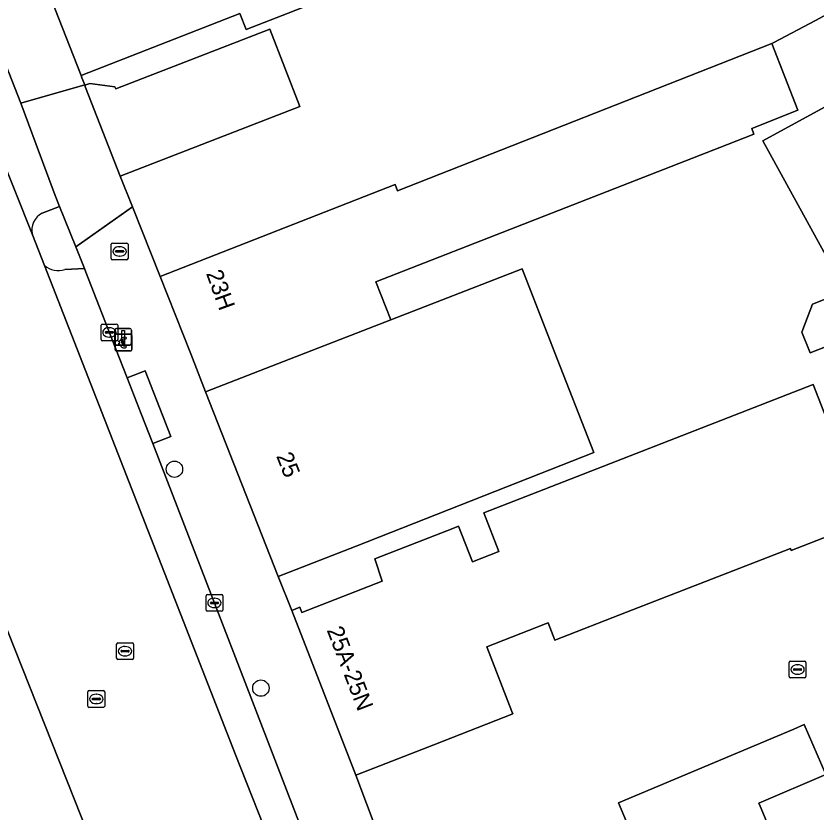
# Model space of a CAD drawing. Extents: x 161087 to 161926, y 382572 to 383873.
# Drawn here: x 161741.12 to 161788.94, y 382710.1 to 382757.68 of the extents above; entities that cross this region are included whole.
import ezdxf

# ---------------------------------------------------------------- set-up
doc = ezdxf.new("R2010")
doc.units = 0
for name, color, linetype in [('IMGEO_Betaalautomaat', 7, 'Continuous'), ('IMGEO_Boom', 7, 'Continuous'), ('IMGEO_Brandkraan', 7, 'Continuous'), ('IMGEO_Erf', 7, 'Continuous'), ('IMGEO_Kolk', 7, 'Continuous'), ('IMGEO_Lichtmast', 7, 'Continuous'), ('IMGEO_Pand', 7, 'Continuous'), ('IMGEO_Pand_nummerreeks', 7, 'Continuous'), ('IMGEO_Pand_overbouw', 7, 'Continuous'), ('IMGEO_Parkeervlak_open', 7, 'Continuous'), ('IMGEO_Rijbaan_lokaal_open', 7, 'Continuous'), ('IMGEO_Rioolput', 7, 'Continuous'), ('IMGEO_Voetpad_open', 7, 'Continuous')]:
    doc.layers.add(name, color=color, linetype=linetype)

msp = doc.modelspace()

# ---------------------------------------------------------------- linework, layer by layer
at = {"layer": 'IMGEO_Betaalautomaat'}
for p, q in [((161747.115, 382738.666), (161747.956, 382738.666)), ((161747.956, 382738.666), (161747.115, 382738.666)), ((161747.04, 382737.742), (161747.04, 382738.583)), ((161747.04, 382738.583), (161747.04, 382737.742)), ((161747.323, 382738.13), (161747.323, 382738.198)), ((161747.444, 382738.198), (161747.444, 382738.13)), ((161747.702, 382738.471), (161747.685, 382738.371)), ((161748.039, 382738.592), (161748.039, 382737.751)), ((161748.039, 382737.751), (161748.039, 382738.592)), ((161747.689, 382737.965), (161747.711, 382737.878)), ((161747.965, 382737.667), (161747.124, 382737.667)), ((161747.124, 382737.667), (161747.965, 382737.667))]:
    msp.add_line(p, q, dxfattribs=at)
for points in [[(161747.323, 382738.198), (161747.254, 382738.198), (161747.254, 382738.267), (161747.333, 382738.267)], [(161747.455, 382738.267), (161747.602, 382738.267), (161747.602, 382738.198), (161747.444, 382738.198)], [(161747.328, 382738.061), (161747.254, 382738.061), (161747.254, 382738.13), (161747.323, 382738.13)], [(161747.444, 382738.13), (161747.602, 382738.13), (161747.602, 382738.061), (161747.458, 382738.061)]]:
    msp.add_lwpolyline(points, dxfattribs=at)
for centre, radius, start, end in [((161747.118, 382738.589), 0.0779, 92.4484, 184.2845), ((161747.118, 382738.589), 0.0779, 92.4484, 184.2845), ((161747.962, 382738.589), 0.0779, 2.4484, 94.2845), ((161747.962, 382738.589), 0.0779, 2.4484, 94.2845), ((161747.616, 382738.191), 0.293, 73.014, 165.0139), ((161747.622, 382738.204), 0.179, 69.3236, 159.5683), ((161747.118, 382737.745), 0.0779, 182.4484, 274.2845), ((161747.118, 382737.745), 0.0779, 182.4484, 274.2845), ((161747.589, 382738.116), 0.267, 191.8096, 297.0389), ((161747.622, 382738.131), 0.179, 202.7625, 291.8693), ((161747.962, 382737.745), 0.0779, 272.4484, 4.2845), ((161747.962, 382737.745), 0.0779, 272.4484, 4.2845)]:
    msp.add_arc(centre, radius, start, end, dxfattribs=at)
at = {"layer": 'IMGEO_Boom'}
for centre in [(161750.589, 382730.591), (161755.753, 382717.503)]:
    msp.add_circle(centre, 0.489, dxfattribs=at)
at = {"layer": 'IMGEO_Brandkraan'}
for p, q in [((161746.811, 382743.187), (161746.811, 382744.039)), ((161746.886, 382744.113), (161747.738, 382744.113)), ((161747.812, 382744.039), (161747.812, 382743.187)), ((161747.07, 382743.607), (161747.07, 382743.619)), ((161747.508, 382743.57), (161747.11, 382743.57)), ((161747.113, 382743.656), (161747.511, 382743.656)), ((161747.299, 382743.893), (161747.324, 382743.893)), ((161747.554, 382743.619), (161747.554, 382743.607)), ((161747.738, 382743.113), (161746.886, 382743.113)), ((161747.322, 382743.333), (161747.297, 382743.333))]:
    msp.add_line(p, q, dxfattribs=at)
for points in [[(161746.811, 382743.187), (161746.811, 382744.039)], [(161746.886, 382744.113), (161747.738, 382744.113)], [(161747.812, 382744.039), (161747.812, 382743.187)], [(161747.738, 382743.113), (161746.886, 382743.113)]]:
    msp.add_lwpolyline(points, dxfattribs=at)
for centre, radius, start, end in [((161746.888, 382744.037), 0.0765, 91.552, 178.448), ((161746.888, 382744.037), 0.0765, 91.552, 178.448), ((161747.736, 382744.037), 0.0765, 1.552, 88.448), ((161747.736, 382744.037), 0.0765, 1.552, 88.448), ((161747.11, 382743.616), 0.0403, 85.8775, 175.7526), ((161747.107, 382743.606), 0.0366, 178.938, 274.7102), ((161747.511, 382743.613), 0.043, 264.8664, 352.4533), ((161747.515, 382743.618), 0.0386, 1.7309, 96.639), ((161746.888, 382743.189), 0.0765, 181.552, 268.448), ((161746.888, 382743.189), 0.0765, 181.552, 268.448), ((161747.736, 382743.189), 0.0765, 271.552, 358.448), ((161747.736, 382743.189), 0.0765, 271.552, 358.448)]:
    msp.add_arc(centre, radius, start, end, dxfattribs=at)
for centre, major_axis, ratio, start_param, end_param in [((161747.298, 382743.613), (-0.387, 0.002), 0.722429, 4.712389, 7.853982), ((161747.323, 382743.613), (-0.39, 0.002), 0.717154, 1.570796, 4.712389)]:
    msp.add_ellipse(centre, major_axis=major_axis, ratio=ratio, start_param=start_param, end_param=end_param, dxfattribs=at)
at = {"layer": 'IMGEO_Erf'}
for points in [[(161792.002, 382759.112), (161788.908, 382757.413), (161786.424, 382756.091), (161786.294, 382756.038), (161787.843, 382752.05), (161785.092, 382750.952), (161785.222, 382750.626), (161783.647, 382750), (161762.633, 382741.801), (161763.515, 382739.519), (161771.376, 382742.575), (161773.294, 382737.652), (161775.656, 382731.589), (161769.742, 382729.263), (161761.442, 382725.999), (161756.788, 382724.168), (161757.599, 382722.152), (161758.076, 382722.338), (161758.198, 382722.024), (161762.996, 382723.894), (161762.56, 382725.236), (161767.219, 382727.052), (161767.568, 382727.188), (161768.401, 382725.051), (161769.983, 382725.667), (161769.081, 382727.983), (161772.311, 382729.242), (161788.77, 382735.655), (161791.956, 382727.48), (161787.457, 382725.726), (161787.405, 382725.859), (161777.602, 382722.04), (161773.321, 382720.372), (161772.921, 382721.4), (161772.775, 382721.343), (161771.752, 382720.945), (161769.259, 382719.973), (161770.763, 382716.112), (161770.821, 382715.962), (161766.092, 382714.119), (161761.433, 382712.304), (161771.278, 382686.152)], [(161778.153, 382708.232), (161777.137, 382710.655), (161787.603, 382715.06), (161788.237, 382715.327), (161789.523, 382712.339), (161785.528, 382710.619), (161785.598, 382710.452), (161787.258, 382706.492)]]:
    msp.add_lwpolyline(points, dxfattribs=at)
for points in [[(161758.09, 382752.271), (161756.299, 382756.897), (161747.078, 382753.327), (161747.027, 382753.458), (161745.521, 382753.653), (161745.232, 382753.541), (161745.281, 382753.416), (161747.346, 382748.113)], [(161797.962, 382728.415), (161797.788, 382728.319), (161785.753, 382750.218), (161791.191, 382753.197), (161793.435, 382754.427), (161794.2, 382753.036), (161798.607, 382745.023), (161799.005, 382744.299), (161797.372, 382743.432), (161798.28, 382741.775), (161799.902, 382742.664), (161800.287, 382741.962), (161804.675, 382733.953), (161805.453, 382732.533)], [(161788.579, 382737.55), (161788.088, 382738.792), (161788.733, 382740.452), (161790.249, 382741.048), (161791.235, 382738.594)]]:
    msp.add_lwpolyline(points, close=True, dxfattribs=at)
at = {"layer": 'IMGEO_Kolk'}
for p, q in [((161746.198, 382738.345), (161746.198, 382739.197)), ((161746.273, 382739.271), (161747.125, 382739.271)), ((161747.199, 382739.197), (161747.199, 382738.345)), ((161746.457, 382738.765), (161746.457, 382738.777)), ((161746.895, 382738.728), (161746.497, 382738.728)), ((161746.5, 382738.814), (161746.898, 382738.814)), ((161746.686, 382739.051), (161746.711, 382739.051)), ((161746.941, 382738.777), (161746.941, 382738.765)), ((161747.125, 382738.271), (161746.273, 382738.271)), ((161746.709, 382738.491), (161746.684, 382738.491)), ((161752.476, 382722.17), (161752.476, 382723.022)), ((161752.551, 382723.096), (161753.403, 382723.096)), ((161752.964, 382722.876), (161752.989, 382722.876)), ((161753.477, 382723.022), (161753.477, 382722.17)), ((161752.735, 382722.59), (161752.735, 382722.602)), ((161753.173, 382722.553), (161752.775, 382722.553)), ((161752.778, 382722.639), (161753.176, 382722.639)), ((161753.219, 382722.602), (161753.219, 382722.59)), ((161753.403, 382722.096), (161752.551, 382722.096)), ((161752.987, 382722.316), (161752.962, 382722.316)), ((161787.335, 382718.192), (161787.335, 382719.044)), ((161787.41, 382719.118), (161788.262, 382719.118)), ((161788.336, 382719.044), (161788.336, 382718.192)), ((161787.594, 382718.612), (161787.594, 382718.624)), ((161788.032, 382718.575), (161787.634, 382718.575)), ((161787.637, 382718.661), (161788.035, 382718.661)), ((161787.823, 382718.898), (161787.848, 382718.898)), ((161788.078, 382718.624), (161788.078, 382718.612)), ((161788.262, 382718.118), (161787.41, 382718.118)), ((161787.846, 382718.338), (161787.821, 382718.338))]:
    msp.add_line(p, q, dxfattribs=at)
for points in [[(161746.198, 382738.345), (161746.198, 382739.197)], [(161746.273, 382739.271), (161747.125, 382739.271)], [(161747.199, 382739.197), (161747.199, 382738.345)], [(161747.125, 382738.271), (161746.273, 382738.271)], [(161752.476, 382722.17), (161752.476, 382723.022)], [(161752.551, 382723.096), (161753.403, 382723.096)], [(161753.477, 382723.022), (161753.477, 382722.17)], [(161753.403, 382722.096), (161752.551, 382722.096)], [(161787.335, 382718.192), (161787.335, 382719.044)], [(161787.41, 382719.118), (161788.262, 382719.118)], [(161788.336, 382719.044), (161788.336, 382718.192)], [(161788.262, 382718.118), (161787.41, 382718.118)]]:
    msp.add_lwpolyline(points, dxfattribs=at)
for centre, radius, start, end in [((161746.275, 382739.195), 0.0765, 91.552, 178.448), ((161746.275, 382739.195), 0.0765, 91.552, 178.448), ((161747.123, 382739.195), 0.0765, 1.552, 88.448), ((161747.123, 382739.195), 0.0765, 1.552, 88.448), ((161746.497, 382738.774), 0.0403, 85.8775, 175.7526), ((161746.494, 382738.764), 0.0366, 178.938, 274.7102), ((161746.898, 382738.771), 0.043, 264.8664, 352.4533), ((161746.902, 382738.776), 0.0386, 1.7309, 96.639), ((161746.275, 382738.347), 0.0765, 181.552, 268.448), ((161746.275, 382738.347), 0.0765, 181.552, 268.448), ((161747.123, 382738.347), 0.0765, 271.552, 358.448), ((161747.123, 382738.347), 0.0765, 271.552, 358.448), ((161752.553, 382723.02), 0.0765, 91.552, 178.448), ((161752.553, 382723.02), 0.0765, 91.552, 178.448), ((161753.401, 382723.02), 0.0765, 1.552, 88.448), ((161753.401, 382723.02), 0.0765, 1.552, 88.448), ((161752.775, 382722.599), 0.0403, 85.8775, 175.7526), ((161752.772, 382722.589), 0.0366, 178.938, 274.7102), ((161753.176, 382722.596), 0.043, 264.8664, 352.4533), ((161753.18, 382722.601), 0.0386, 1.7309, 96.639), ((161752.553, 382722.172), 0.0765, 181.552, 268.448), ((161752.553, 382722.172), 0.0765, 181.552, 268.448), ((161753.401, 382722.172), 0.0765, 271.552, 358.448), ((161753.401, 382722.172), 0.0765, 271.552, 358.448), ((161787.412, 382719.042), 0.0765, 91.552, 178.448), ((161787.412, 382719.042), 0.0765, 91.552, 178.448), ((161788.26, 382719.042), 0.0765, 1.552, 88.448), ((161788.26, 382719.042), 0.0765, 1.552, 88.448), ((161787.634, 382718.621), 0.0403, 85.8775, 175.7526), ((161787.631, 382718.611), 0.0366, 178.938, 274.7102), ((161788.035, 382718.618), 0.043, 264.8664, 352.4533), ((161788.039, 382718.623), 0.0386, 1.7309, 96.639), ((161787.412, 382718.194), 0.0765, 181.552, 268.448), ((161787.412, 382718.194), 0.0765, 181.552, 268.448), ((161788.26, 382718.194), 0.0765, 271.552, 358.448), ((161788.26, 382718.194), 0.0765, 271.552, 358.448)]:
    msp.add_arc(centre, radius, start, end, dxfattribs=at)
for centre, major_axis, ratio, start_param, end_param in [((161746.685, 382738.771), (-0.387, 0.002), 0.722429, 4.712389, 7.853982), ((161746.71, 382738.771), (-0.39, 0.002), 0.717154, 1.570796, 4.712389), ((161752.963, 382722.596), (-0.387, 0.002), 0.722429, 4.712389, 7.853982), ((161752.988, 382722.596), (-0.39, 0.002), 0.717154, 1.570796, 4.712389), ((161787.822, 382718.618), (-0.387, 0.002), 0.722429, 4.712389, 7.853982), ((161787.847, 382718.618), (-0.39, 0.002), 0.717154, 1.570796, 4.712389)]:
    msp.add_ellipse(centre, major_axis=major_axis, ratio=ratio, start_param=start_param, end_param=end_param, dxfattribs=at)
at = {"layer": 'IMGEO_Lichtmast'}
for p, q in [((161747.029, 382738.109), (161747.029, 382738.909)), ((161747.029, 382738.909), (161747.029, 382738.109)), ((161747.129, 382739.009), (161747.919, 382739.009)), ((161747.919, 382739.009), (161747.129, 382739.009)), ((161748.019, 382738.909), (161748.019, 382738.109)), ((161748.019, 382738.109), (161748.019, 382738.909)), ((161747.919, 382738.009), (161747.129, 382738.009)), ((161747.129, 382738.009), (161747.919, 382738.009))]:
    msp.add_line(p, q, dxfattribs=at)
msp.add_lwpolyline([(161747.449, 382738.884), (161747.599, 382738.884), (161747.599, 382738.134), (161747.449, 382738.134), (161747.449, 382738.884)], dxfattribs=at)
for centre, start, end in [((161747.129, 382738.909), 90, 180), ((161747.129, 382738.909), 90, 180), ((161747.919, 382738.909), 0, 90), ((161747.919, 382738.909), 360, 90), ((161747.129, 382738.109), 180, 270), ((161747.129, 382738.109), 180, 270), ((161747.919, 382738.109), 270, 0), ((161747.919, 382738.109), 270, 0)]:
    msp.add_arc(centre, 0.1, start, end, dxfattribs=at)
at = {"layer": 'IMGEO_Pand'}
for points in [[(161778.916, 382776.105), (161778.137, 382776.023), (161774.502, 382785.469), (161764.744, 382784.333), (161765.335, 382779.309), (161753.095, 382778.125), (161744.443, 382777.251), (161737.071, 382774.806), (161737.155, 382774.582), (161736.997, 382774.519), (161739.569, 382768.038), (161740.865, 382764.716), (161742.992, 382759.27), (161745.004, 382754.118), (161754.496, 382757.83), (161754.87, 382756.874), (161760.362, 382759.021), (161782.19, 382767.438), (161781.539, 382769.143)], [(161783.647, 382750), (161785.222, 382750.626), (161785.092, 382750.952), (161787.843, 382752.05), (161786.294, 382756.038), (161763.929, 382747.233), (161763.782, 382747.61), (161749.728, 382742.115), (161751.568, 382737.483), (161752.444, 382735.215), (161757.105, 382737.027), (161763.515, 382739.519), (161762.633, 382741.801)], [(161794.2, 382753.036), (161793.435, 382754.427), (161791.191, 382753.197), (161785.753, 382750.218), (161797.788, 382728.319), (161797.962, 382728.415), (161805.453, 382732.533), (161804.675, 382733.953), (161800.287, 382741.962), (161799.902, 382742.664), (161798.28, 382741.775), (161797.372, 382743.432), (161799.005, 382744.299), (161798.607, 382745.023)], [(161773.294, 382737.652), (161771.376, 382742.575), (161763.515, 382739.519), (161757.105, 382737.027), (161752.444, 382735.215), (161756.788, 382724.168), (161761.442, 382725.999), (161769.742, 382729.263), (161775.656, 382731.589)], [(161790.249, 382741.048), (161788.733, 382740.452), (161788.088, 382738.792), (161788.579, 382737.55), (161791.235, 382738.594)], [(161787.405, 382725.859), (161787.457, 382725.726), (161791.956, 382727.48), (161788.77, 382735.655), (161772.311, 382729.242), (161769.081, 382727.983), (161769.983, 382725.667), (161768.401, 382725.051), (161767.568, 382727.188), (161767.219, 382727.052), (161762.56, 382725.236), (161762.996, 382723.894), (161758.198, 382722.024), (161758.076, 382722.338), (161757.599, 382722.152), (161761.433, 382712.304), (161766.092, 382714.119), (161770.821, 382715.962), (161770.763, 382716.112), (161769.259, 382719.973), (161771.752, 382720.945), (161772.775, 382721.343), (161772.921, 382721.4), (161773.321, 382720.372), (161777.602, 382722.04)], [(161787.005, 382699.938), (161784.706, 382705.422), (161787.258, 382706.492), (161785.598, 382710.452), (161785.528, 382710.619), (161789.523, 382712.339), (161788.237, 382715.327), (161787.603, 382715.06), (161777.137, 382710.655), (161778.153, 382708.232), (161774.101, 382706.534), (161778.499, 382696.044), (161786.485, 382699.392), (161786.368, 382699.671)]]:
    msp.add_lwpolyline(points, close=True, dxfattribs=at)
msp.add_lwpolyline([(161760.362, 382759.021), (161754.87, 382756.874), (161754.496, 382757.83), (161745.004, 382754.118), (161745.052, 382753.994), (161745.224, 382753.561), (161745.232, 382753.541), (161745.521, 382753.653), (161747.027, 382753.458), (161747.078, 382753.327), (161756.299, 382756.897), (161758.09, 382752.271), (161747.346, 382748.113), (161748.078, 382746.268), (161749.728, 382742.115), (161763.782, 382747.61), (161763.929, 382747.233), (161786.294, 382756.038), (161786.424, 382756.091), (161788.908, 382757.413), (161792.002, 382759.112)], dxfattribs=at)
at = {"layer": 'IMGEO_Pand_overbouw'}
msp.add_lwpolyline([(161756.299, 382756.897), (161747.078, 382753.327), (161747.027, 382753.458), (161745.521, 382753.653), (161745.232, 382753.541), (161745.281, 382753.416), (161747.346, 382748.113), (161758.09, 382752.271)], close=True, dxfattribs=at)
at = {"layer": 'IMGEO_Parkeervlak_open'}
for points in [[(161727.579, 382786.223), (161727.028, 382786.484), (161725.319, 382787.311), (161739.937, 382750), (161742.111, 382744.609)], [(161742.688, 382745.897), (161743.726, 382746.292), (161743.459, 382746.961), (161742.323, 382750), (161741.399, 382752.473), (161738.911, 382758.814)], [(161742.826, 382742.772), (161754.209, 382713.572), (161768.441, 382677.581), (161785.32, 382634.34), (161787.244, 382635.106), (161780.81, 382651.335), (161778.239, 382657.862), (161774.899, 382666.339), (161773.946, 382668.758), (161770.928, 382676.475), (161768.074, 382683.775), (161767.169, 382686.089), (161763.685, 382694.956), (161761.824, 382699.694), (161761.163, 382701.376), (161759.331, 382706.124), (161758.324, 382708.735), (161755.146, 382716.973)], [(161755.146, 382716.973), (161750.176, 382729.847), (161749.294, 382732.127), (161748.608, 382733.899), (161747.764, 382736.047), (161747.065, 382737.827), (161745.292, 382742.374), (161745.204, 382742.595), (161744.027, 382742.521)]]:
    msp.add_lwpolyline(points, dxfattribs=at)
for centre, radius, start, end in [((161743.151, 382744.916), 1.084, 115.2602, 196.4768), ((161743.645, 382743.694), 1.233, 228.3675, 288.0235)]:
    msp.add_arc(centre, radius, start, end, dxfattribs=at)
at = {"layer": 'IMGEO_Rijbaan_lokaal_open'}
for points in [[(161754.209, 382713.572), (161742.826, 382742.772), (161742.111, 382744.609), (161739.937, 382750), (161725.319, 382787.311), (161724.087, 382787.908)], [(161739.688, 382723.21), (161746.805, 382705.307), (161749.972, 382697.162), (161751.621, 382697.849), (161763.88, 382666.739), (161774.224, 382639.932)], [(161746.805, 382705.307), (161739.688, 382723.21)], [(161789.785, 382625.062), (161790.242, 382626.794), (161790.211, 382627.501), (161789.724, 382628.692), (161789.273, 382629.791), (161788.28, 382632.38), (161787.244, 382635.106), (161785.32, 382634.34), (161768.441, 382677.581), (161754.209, 382713.572)]]:
    msp.add_lwpolyline(points, dxfattribs=at)
at = {"layer": 'IMGEO_Rioolput'}
for p, q in [((161747.133, 382719.287), (161747.133, 382720.139)), ((161747.208, 382720.213), (161748.06, 382720.213)), ((161747.621, 382719.993), (161747.646, 382719.993)), ((161748.134, 382720.139), (161748.134, 382719.287)), ((161747.392, 382719.707), (161747.392, 382719.719)), ((161747.83, 382719.67), (161747.432, 382719.67)), ((161747.435, 382719.756), (161747.833, 382719.756)), ((161747.876, 382719.719), (161747.876, 382719.707)), ((161748.06, 382719.213), (161747.208, 382719.213)), ((161747.644, 382719.433), (161747.619, 382719.433)), ((161745.417, 382716.43), (161745.417, 382717.282)), ((161745.492, 382717.356), (161746.344, 382717.356)), ((161745.905, 382717.136), (161745.93, 382717.136)), ((161746.418, 382717.282), (161746.418, 382716.43)), ((161745.676, 382716.85), (161745.676, 382716.862)), ((161746.114, 382716.813), (161745.716, 382716.813)), ((161745.719, 382716.899), (161746.117, 382716.899)), ((161746.16, 382716.862), (161746.16, 382716.85)), ((161746.344, 382716.356), (161745.492, 382716.356)), ((161745.928, 382716.576), (161745.903, 382716.576))]:
    msp.add_line(p, q, dxfattribs=at)
for points in [[(161747.133, 382719.287), (161747.133, 382720.139)], [(161747.208, 382720.213), (161748.06, 382720.213)], [(161748.134, 382720.139), (161748.134, 382719.287)], [(161748.06, 382719.213), (161747.208, 382719.213)], [(161745.417, 382716.43), (161745.417, 382717.282)], [(161745.492, 382717.356), (161746.344, 382717.356)], [(161746.418, 382717.282), (161746.418, 382716.43)], [(161746.344, 382716.356), (161745.492, 382716.356)]]:
    msp.add_lwpolyline(points, dxfattribs=at)
for centre, radius, start, end in [((161747.21, 382720.137), 0.0765, 91.552, 178.448), ((161747.21, 382720.137), 0.0765, 91.552, 178.448), ((161748.058, 382720.137), 0.0765, 1.552, 88.448), ((161748.058, 382720.137), 0.0765, 1.552, 88.448), ((161747.432, 382719.716), 0.0403, 85.8775, 175.7526), ((161747.429, 382719.706), 0.0366, 178.938, 274.7102), ((161747.833, 382719.713), 0.043, 264.8664, 352.4533), ((161747.837, 382719.718), 0.0386, 1.7309, 96.639), ((161747.21, 382719.289), 0.0765, 181.552, 268.448), ((161747.21, 382719.289), 0.0765, 181.552, 268.448), ((161748.058, 382719.289), 0.0765, 271.552, 358.448), ((161748.058, 382719.289), 0.0765, 271.552, 358.448), ((161745.494, 382717.28), 0.0765, 91.552, 178.448), ((161745.494, 382717.28), 0.0765, 91.552, 178.448), ((161746.342, 382717.28), 0.0765, 1.552, 88.448), ((161746.342, 382717.28), 0.0765, 1.552, 88.448), ((161745.716, 382716.859), 0.0403, 85.8775, 175.7526), ((161745.713, 382716.849), 0.0366, 178.938, 274.7102), ((161746.117, 382716.856), 0.043, 264.8664, 352.4533), ((161746.121, 382716.861), 0.0386, 1.7309, 96.639), ((161745.494, 382716.432), 0.0765, 181.552, 268.448), ((161745.494, 382716.432), 0.0765, 181.552, 268.448), ((161746.342, 382716.432), 0.0765, 271.552, 358.448), ((161746.342, 382716.432), 0.0765, 271.552, 358.448)]:
    msp.add_arc(centre, radius, start, end, dxfattribs=at)
for centre, major_axis, ratio, start_param, end_param in [((161747.62, 382719.713), (-0.387, 0.002), 0.722429, 4.712389, 7.853982), ((161747.645, 382719.713), (-0.39, 0.002), 0.717154, 1.570796, 4.712389), ((161745.904, 382716.856), (-0.387, 0.002), 0.722429, 4.712389, 7.853982), ((161745.929, 382716.856), (-0.39, 0.002), 0.717154, 1.570796, 4.712389)]:
    msp.add_ellipse(centre, major_axis=major_axis, ratio=ratio, start_param=start_param, end_param=end_param, dxfattribs=at)
at = {"layer": 'IMGEO_Voetpad_open'}
for points in [[(161728.103, 382785.675), (161728.876, 382783.671), (161731.258, 382777.93), (161734.093, 382770.766), (161738.911, 382758.814), (161741.399, 382752.473), (161745.224, 382753.561), (161745.052, 382753.994), (161745.004, 382754.118), (161742.992, 382759.27), (161740.865, 382764.716), (161739.569, 382768.038), (161736.997, 382774.519), (161737.155, 382774.582), (161737.071, 382774.806), (161734.55, 382781.557)], [(161743.726, 382746.292), (161742.688, 382745.897)], [(161744.027, 382742.521), (161745.204, 382742.595), (161744.692, 382743.875), (161743.726, 382746.292)], [(161771.278, 382686.152), (161761.433, 382712.304), (161757.599, 382722.152), (161756.788, 382724.168), (161752.444, 382735.215), (161751.568, 382737.483), (161749.728, 382742.115), (161748.078, 382746.268), (161744.692, 382743.875), (161745.204, 382742.595), (161745.292, 382742.374), (161747.065, 382737.827), (161747.764, 382736.047), (161748.835, 382736.465), (161750.365, 382732.545), (161749.294, 382732.127), (161750.176, 382729.847), (161755.146, 382716.973), (161758.324, 382708.735)], [(161742.111, 382744.609), (161742.826, 382742.772)]]:
    msp.add_lwpolyline(points, dxfattribs=at)
for points in [[(161745.281, 382753.416), (161745.232, 382753.541), (161745.224, 382753.561), (161741.399, 382752.473), (161742.323, 382750), (161743.459, 382746.961), (161743.726, 382746.292), (161744.692, 382743.875), (161748.078, 382746.268), (161747.346, 382748.113)], [(161747.764, 382736.047), (161748.608, 382733.899), (161749.294, 382732.127), (161750.365, 382732.545), (161748.835, 382736.465)]]:
    msp.add_lwpolyline(points, close=True, dxfattribs=at)
for centre, radius, start, end in [((161743.151, 382744.916), 1.084, 115.2602, 196.4768), ((161743.645, 382743.694), 1.233, 228.3675, 288.0235)]:
    msp.add_arc(centre, radius, start, end, dxfattribs=at)

# ---------------------------------------------------------------- texts
at = {"layer": 'IMGEO_Pand_nummerreeks'}
for s, rotation, p in [('23H', 289.9831, (161752.463, 382742.304)), ('25', 291.4662, (161756.659, 382731.383)), ('25A-25N', 291.0732, (161759.678, 382720.979))]:
    msp.add_text(s, height=1, rotation=rotation, dxfattribs=at).set_placement(p)

doc.saveas('drawing.dxf')
